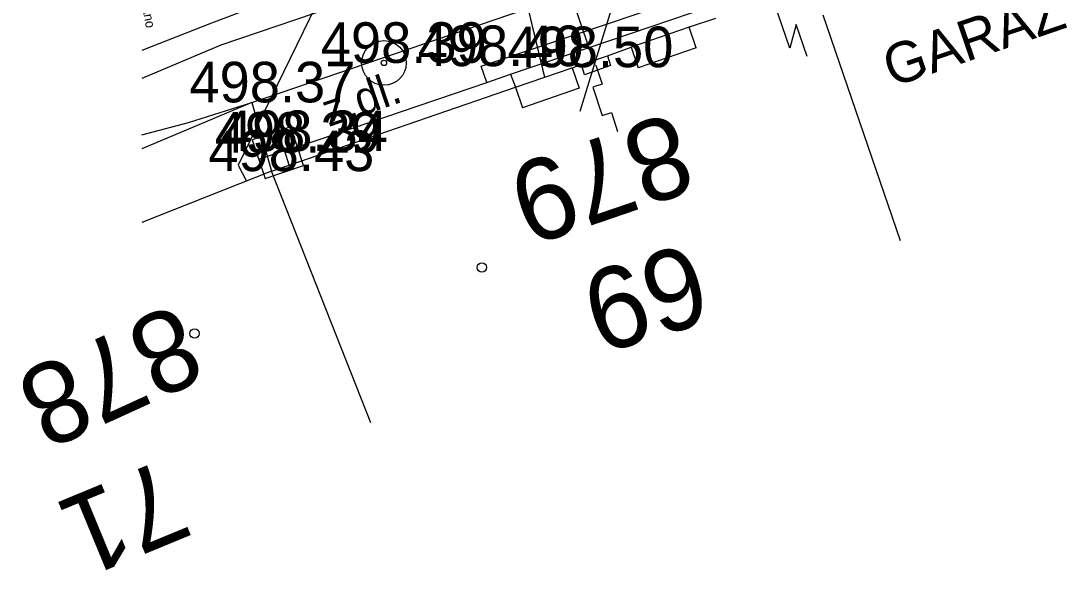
# Model space of a CAD drawing. Extents: x -669642 to -669119, y -1131006 to -1130466.
# Drawn here: x -669642.28 to -669622.94, y -1130651.42 to -1130641.28 of the extents above; entities that cross this region are included whole.
import ezdxf

# ---------------------------------------------------------------- set-up
doc = ezdxf.new("R2010")
doc.units = 0
for name, color, linetype in [('G_Bod_tecka', 7, 'Continuous'), ('G_Bod_vyska', 7, 'Continuous'), ('G_Bodove_pole', 7, 'Continuous'), ('G_Budovy-znacky', 7, 'Continuous'), ('G_Budovy_Objekty', 7, 'Continuous'), ('G_Budovy_vstupy', 7, 'Continuous'), ('G_Cesty_Schody', 7, 'Continuous'), ('G_Cisla_orientacni', 7, 'Continuous'), ('G_Cisla_popisna', 7, 'Continuous'), ('G_Plochy_zpevnene', 7, 'Continuous'), ('G_Ploty', 7, 'Continuous'), ('G_Popisy_objektu', 7, 'Continuous'), ('G_Popisy_povrchu', 7, 'Continuous'), ('G_Site-kanalizace', 7, 'Continuous'), ('G_Site-Rozvadece', 7, 'Continuous'), ('G_Z_ELsilove_nadz_kotovane', 7, 'Continuous'), ('G_Z_ELsilove_zrusene', 7, 'Continuous'), ('G_Z_PLYNY_podz_geodeticky', 7, 'Continuous'), ('G_Z_SPOJE_nadz_kotovane', 7, 'Continuous'), ('G_Z_VODA_podz_kotovane', 7, 'Continuous'), ('Vrstva 26', 7, 'Continuous'), ('Vrstva 3', 7, 'Continuous')]:
    doc.layers.add(name, color=color, linetype=linetype)

msp = doc.modelspace()

# ---------------------------------------------------------------- linework, layer by layer
at = {"layer": 'G_Bod_tecka'}
for p, q in [((-669635.57, -1130642.05), (-669635.57, -1130642.05)), ((-669633.77, -1130642.11), (-669633.77, -1130642.11)), ((-669632.1, -1130642.13), (-669632.1, -1130642.13)), ((-669638.01, -1130642.78), (-669638.01, -1130642.78)), ((-669637.53, -1130643.71), (-669637.53, -1130643.71)), ((-669637.4, -1130643.68), (-669637.4, -1130643.68)), ((-669637.65, -1130644.05), (-669637.65, -1130644.05))]:
    msp.add_line(p, q, dxfattribs=at)
at = {"layer": 'G_Bodove_pole'}
for radius in [0.412, 0.05]:
    msp.add_circle((-669635.57, -1130642.05), radius, dxfattribs=at)
at = {"layer": 'G_Budovy-znacky'}
for centre in [(-669633.759, -1130645.83), (-669639.07, -1130647.05)]:
    msp.add_circle(centre, 0.0875, dxfattribs=at)
at = {"layer": 'G_Budovy_Objekty'}
for p, q in [((-669629.44, -1130641.23), (-669629.93, -1130641.39)), ((-669626.02, -1130645.34), (-669627.45, -1130641.17)), ((-669629.93, -1130641.39), (-669631, -1130641.76)), ((-669629.8, -1130641.77), (-669629.93, -1130641.39)), ((-669631.92, -1130642.08), (-669631.44, -1130641.92)), ((-669631.44, -1130641.92), (-669631, -1130641.76)), ((-669631, -1130641.76), (-669630.87, -1130642.14)), ((-669632.09, -1130642.14), (-669631.92, -1130642.08)), ((-669633.14, -1130642.5), (-669632.09, -1130642.14)), ((-669632.09, -1130642.14), (-669631.96, -1130642.52)), ((-669637.32, -1130643.94), (-669633.14, -1130642.5)), ((-669633.14, -1130642.5), (-669633.01, -1130642.88)), ((-669637.65, -1130644.05), (-669640.046, -1130645)), ((-669637.65, -1130644.05), (-669637.32, -1130643.94)), ((-669635.81, -1130648.7), (-669637.65, -1130644.05))]:
    msp.add_line(p, q, dxfattribs=at)
at = {"layer": 'G_Budovy_vstupy'}
for p, q in [((-669629.8, -1130641.77), (-669630.87, -1130642.14)), ((-669631.96, -1130642.52), (-669633.01, -1130642.88))]:
    msp.add_line(p, q, dxfattribs=at)
at = {"layer": 'G_Cesty_Schody'}
for q in [(-669640.046, -1130643.636), (-669637.65, -1130644.05)]:
    msp.add_line((-669638.01, -1130642.78), q, dxfattribs=at)
for points in [[(-669633.77, -1130642.11), (-669629.62, -1130640.71)], [(-669633.23, -1130642.26), (-669629.52, -1130641)], [(-669633.67, -1130642.41), (-669633.77, -1130642.11)]]:
    msp.add_lwpolyline(points, dxfattribs=at)
at = {"layer": 'G_Plochy_zpevnene'}
msp.add_lwpolyline([(-669640.046, -1130643.381), (-669639.18, -1130643.15), (-669638.01, -1130642.78), (-669632.99, -1130641.07), (-669627.97, -1130639.36)], dxfattribs=at)
at = {"layer": 'G_Ploty'}
for p, q in [((-669633.67, -1130642.41), (-669633.23, -1130642.26)), ((-669633.23, -1130642.26), (-669633.14, -1130642.5)), ((-669637.4, -1130643.68), (-669633.67, -1130642.41)), ((-669637.32, -1130643.94), (-669637.4, -1130643.68))]:
    msp.add_line(p, q, dxfattribs=at)
at = {"layer": 'G_Site-kanalizace'}
msp.add_lwpolyline([(-669637.766, -1130644.184), (-669637.055, -1130643.945), (-669637.294, -1130643.234), (-669638.005, -1130643.473)], close=True, dxfattribs=at)
msp.add_lwpolyline([(-669637.885, -1130643.829), (-669637.174, -1130643.591)], dxfattribs=at)
at = {"layer": 'G_Site-Rozvadece'}
for p, q in [((-669628.066, -1130641.779), (-669628.35, -1130640.951)), ((-669627.951, -1130641.343), (-669628.066, -1130641.779)), ((-669627.748, -1130641.935), (-669627.951, -1130641.343)), ((-669631.44, -1130641.92), (-669631.38, -1130642.1)), ((-669631.86, -1130642.27), (-669631.92, -1130642.08)), ((-669631.38, -1130642.1), (-669631.86, -1130642.27))]:
    msp.add_line(p, q, dxfattribs=at)
msp.add_lwpolyline([(-669631.651, -1130642.091), (-669631.537, -1130642.441), (-669631.711, -1130642.498), (-669631.539, -1130643.022), (-669631.365, -1130642.966), (-669631.25, -1130643.316)], dxfattribs=at)
at = {"layer": 'G_Z_ELsilove_nadz_kotovane'}
msp.add_lwpolyline([(-669631.66, -1130630.39), (-669638.265, -1130643.943), (-669638.112, -1130644.236)], dxfattribs=at)
at = {"layer": 'G_Z_ELsilove_zrusene'}
for points in [[(-669640.046, -1130567.481), (-669635.611, -1130570.817), (-669633.942, -1130573.294), (-669630.223, -1130581.178), (-669629.551, -1130587.927), (-669629.234, -1130594.896), (-669628.644, -1130602.807), (-669628.112, -1130609.531), (-669628.047, -1130610.349), (-669627.643, -1130618.665), (-669627.204, -1130626.418), (-669627.024, -1130632.43), (-669626.985, -1130637.091), (-669627.357, -1130637.75), (-669628.233, -1130638.205), (-669638.584, -1130641.721), (-669640.046, -1130642.34)], [(-669640.046, -1130567.481), (-669635.611, -1130570.817), (-669633.942, -1130573.294), (-669630.223, -1130581.178), (-669629.551, -1130587.927), (-669629.234, -1130594.896), (-669628.644, -1130602.807), (-669628.112, -1130609.531), (-669628.047, -1130610.349), (-669627.643, -1130618.665), (-669627.204, -1130626.418), (-669627.024, -1130632.43), (-669626.985, -1130637.091), (-669627.357, -1130637.75), (-669628.233, -1130638.205), (-669638.584, -1130641.721), (-669640.046, -1130642.34)], [(-669640.046, -1130568.206), (-669636.413, -1130571.107), (-669634.512, -1130573.604), (-669630.929, -1130581.06), (-669630.253, -1130587.997), (-669629.948, -1130594.874), (-669629.36, -1130602.959), (-669628.815, -1130608.586), (-669628.653, -1130610.26), (-669628.237, -1130618.672), (-669627.816, -1130626.573), (-669627.465, -1130632.468), (-669627.592, -1130636.717), (-669627.899, -1130637.106), (-669628.536, -1130637.449), (-669638.76, -1130641.316), (-669640.046, -1130641.822)], [(-669640.046, -1130568.206), (-669636.413, -1130571.107), (-669634.512, -1130573.604), (-669630.929, -1130581.06), (-669630.253, -1130587.997), (-669629.948, -1130594.874), (-669629.36, -1130602.959), (-669628.815, -1130608.586), (-669628.653, -1130610.26), (-669628.237, -1130618.672), (-669627.816, -1130626.573), (-669627.465, -1130632.468), (-669627.592, -1130636.717), (-669627.899, -1130637.106), (-669628.536, -1130637.449), (-669638.76, -1130641.316), (-669640.046, -1130641.822)]]:
    msp.add_lwpolyline(points, dxfattribs=at)
at = {"layer": 'G_Z_PLYNY_podz_geodeticky'}
msp.add_lwpolyline([(-669633.72, -1130636.12), (-669631.67, -1130642.09)], dxfattribs=at)
at = {"layer": 'G_Z_SPOJE_nadz_kotovane'}
msp.add_lwpolyline([(-669626.87, -1130626.42), (-669631.95, -1130642.95)], dxfattribs=at)
at = {"layer": 'G_Z_VODA_podz_kotovane'}
msp.add_lwpolyline([(-669633.8, -1130637.84), (-669633.75, -1130637.94), (-669633.45, -1130638.77), (-669632.6, -1130642.32)], dxfattribs=at)
at = {"layer": 'Vrstva 26'}
msp.add_lwpolyline([(-669633.803, -1130637.835), (-669633.747, -1130637.939), (-669633.452, -1130638.772), (-669632.605, -1130642.315)], dxfattribs=at)

# ---------------------------------------------------------------- texts
at = {"layer": 'G_Bod_vyska'}
for s, p in [('498.39', (-669636.738, -1130642.05)), ('498.40', (-669634.948, -1130642.11)), ('498.50', (-669633.288, -1130642.13)), ('498.37', (-669639.166, -1130642.78)), ('498.29', (-669638.698, -1130643.71)), ('498.34', (-669638.566, -1130643.68)), ('498.43', (-669638.816, -1130644.05))]:
    msp.add_text(s, height=0.75, dxfattribs=at).set_placement(p)
at = {"layer": 'G_Cisla_orientacni'}
for s, rotation, p in [('69', 196.8072, (-669629.876, -1130645.357)), ('71', 202.4652, (-669639.619, -1130649.348))]:
    msp.add_text(s, height=1.5, rotation=rotation, dxfattribs=at).set_placement(p)
at = {"layer": 'G_Cisla_popisna'}
for s, rotation, p in [('879', 198.8964, (-669630.204, -1130642.944)), ('878', 204.5127, (-669639.402, -1130646.472))]:
    msp.add_text(s, height=1.5, rotation=rotation, dxfattribs=at).set_placement(p)
at = {"layer": 'G_Popisy_objektu'}
msp.add_text('GARÁŽ', height=0.75, rotation=18.8915, dxfattribs=at).set_placement((-669626.182, -1130642.506))
at = {"layer": 'G_Popisy_povrchu'}
msp.add_text('z.dl.', height=0.6, rotation=18.8046, dxfattribs=at).set_placement((-669636.593, -1130643.236))
at = {"layer": 'Vrstva 3'}
msp.add_text('neuveden nezadáno', height=0.17551, rotation=280.6944, dxfattribs=at).set_placement((-669640.359, -1130639.326))

doc.saveas('drawing.dxf')
